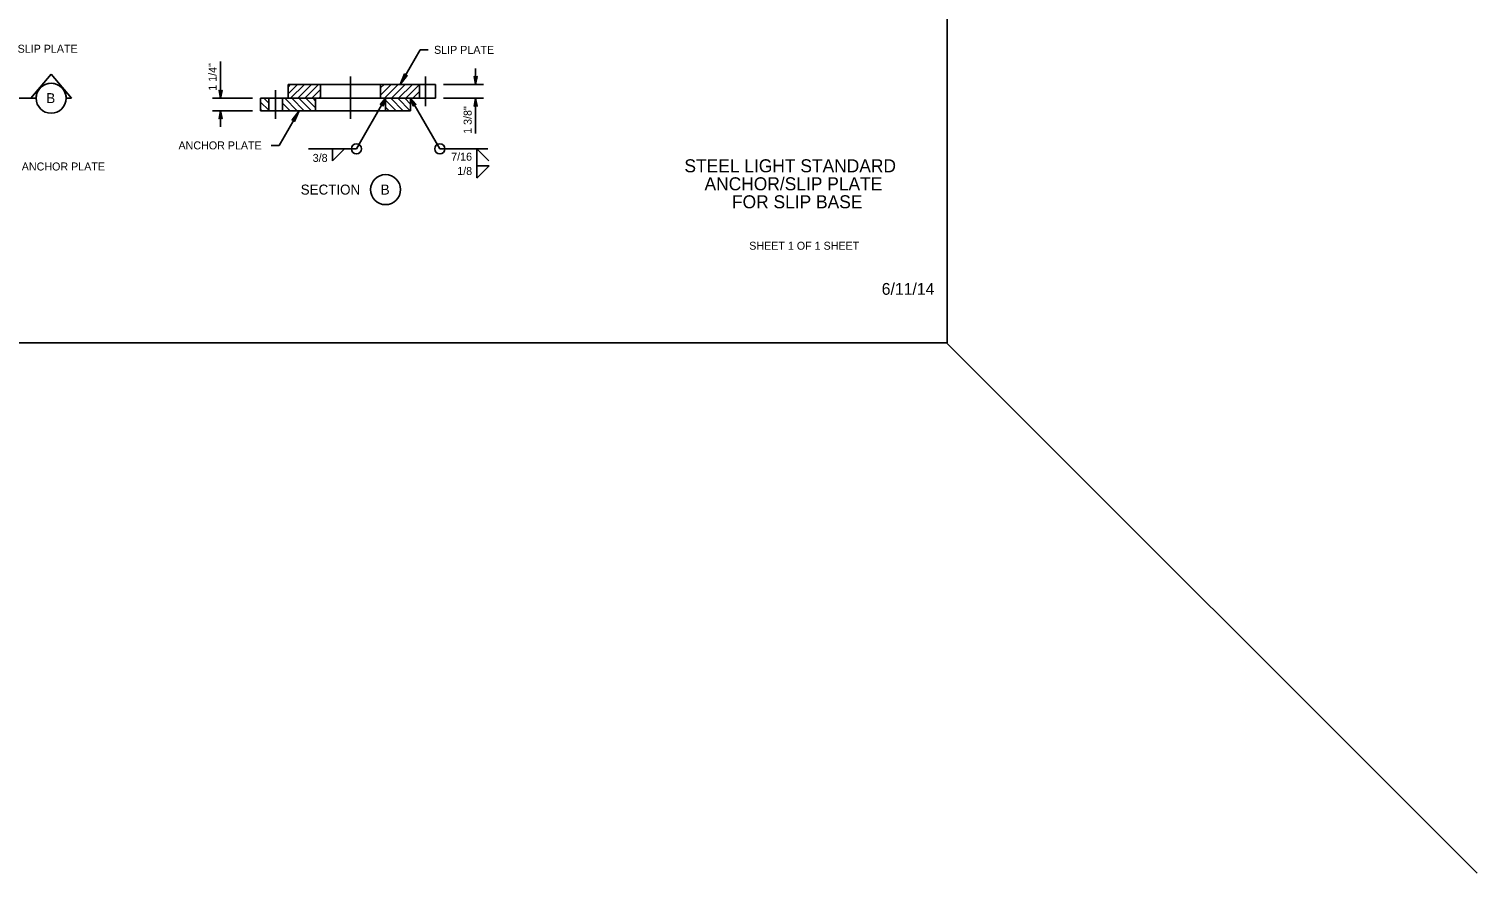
# Model space of a CAD drawing. Extents: x 99862 to 104211, y 98939 to 102076.
# Drawn here: x 101315 to 104211, y 98939 to 100627 of the extents above; entities that cross this region are included whole.
import ezdxf

# ---------------------------------------------------------------- set-up
doc = ezdxf.new("R2010")
doc.units = 0
for name, color, linetype in [('Level 1', 7, 'Continuous'), ('Level 10', 7, 'Continuous'), ('Level 15', 7, 'Continuous'), ('Level 20', 7, 'Continuous'), ('Level 3', 7, 'Continuous'), ('Level 4', 7, 'Continuous'), ('Level 62', 7, 'Continuous'), ('Level 63', 7, 'Continuous'), ('Level 9', 7, 'Continuous')]:
    doc.layers.add(name, color=color, linetype=linetype)

msp = doc.modelspace()

# ---------------------------------------------------------------- linework, layer by layer
at = {"layer": 'Level 1'}
msp.add_line((103150, 100000), (104210.7, 98939.3), dxfattribs=at)
msp.add_lwpolyline([(99862, 99999.5), (103151, 99999.5), (103151, 102075.5), (99862, 102075.5)], close=True, dxfattribs=at)
at = {"layer": 'Level 10'}
for p, q in [((102028.4, 100488.9), (101970, 100387.7)), ((102078.4, 100488.9), (102136.8, 100387.7)), ((101970, 100387.7), (101874, 100387.7)), ((101922, 100387.7), (101922, 100363.7)), ((101946.2, 100387.7), (101922, 100363.5)), ((102136.8, 100387.7), (102232.8, 100387.7)), ((102211, 100353.5), (102211, 100387.7)), ((102235, 100363.5), (102211, 100387.5)), ((102211, 100353.5), (102211, 100329.5)), ((102235.2, 100353.5), (102211, 100329.3)), ((102211, 100353.5), (102235.2, 100353.5))]:
    msp.add_line(p, q, dxfattribs=at)
for points in [[(102028.4, 100488.9), (102017.9, 100476.8), (102020.9, 100475.9), (102023.2, 100473.7)], [(102078.4, 100488.9), (102088.9, 100476.8), (102085.9, 100475.9), (102083.6, 100473.7)]]:
    msp.add_lwpolyline(points, close=True, dxfattribs=at)
for centre in [(101970, 100387.7), (102136.8, 100387.7)]:
    msp.add_circle(centre, 10, dxfattribs=at)
at = {"layer": 'Level 15'}
for p, q in [((101698.4, 100562.7), (101698.4, 100488.9)), ((102057.2, 100516.4), (102097.2, 100585.7)), ((102097.2, 100585.7), (102113.2, 100585.7)), ((101958.4, 100447.9), (101958.4, 100532.4)), ((102108.4, 100472.9), (102108.4, 100532.4)), ((102208.4, 100516.4), (102208.4, 100548.4)), ((101808.4, 100447.9), (101808.4, 100504.9)), ((102144.4, 100516.4), (102224.4, 100516.4)), ((101682.4, 100488.9), (101762.4, 100488.9)), ((102144.4, 100488.9), (102224.4, 100488.9)), ((102208.4, 100418.4), (102208.4, 100488.9)), ((101682.4, 100463.9), (101762.4, 100463.9)), ((101698.4, 100463.9), (101698.4, 100431.9)), ((101855.3, 100463.9), (101815.3, 100394.6)), ((101815.3, 100394.6), (101799.3, 100394.6))]:
    msp.add_line(p, q, dxfattribs=at)
for points in [[(102057.2, 100516.4), (102066, 100537.6), (102068, 100535.2), (102071.2, 100534.7)], [(102208.4, 100516.4), (102205.3, 100532.1), (102208.4, 100531.4), (102211.5, 100532.1)], [(101698.4, 100488.9), (101695.3, 100504.6), (101698.4, 100503.9), (101701.5, 100504.6)], [(102208.4, 100488.9), (102205.3, 100473.1), (102208.4, 100473.9), (102211.5, 100473.1)], [(101698.4, 100463.9), (101695.3, 100448.1), (101698.4, 100448.9), (101701.5, 100448.1)], [(101855.3, 100463.9), (101846.5, 100442.6), (101844.4, 100445), (101841.3, 100445.6)]]:
    msp.add_lwpolyline(points, close=True, dxfattribs=at)
at = {"layer": 'Level 3'}
for p, q in [((101778.4, 100481.1), (101794.7, 100464.9)), ((101784.8, 100488.9), (101794.7, 100479)), ((101794.7, 100488.9), (101822.2, 100488.9)), ((101822.2, 100479.2), (101837.5, 100463.9)), ((101826.6, 100488.9), (101851.6, 100463.9)), ((101840.8, 100488.9), (101865.8, 100463.9)), ((101854.9, 100488.9), (101879.9, 100463.9)), ((101869, 100488.9), (101888.4, 100469.5)), ((101883.2, 100488.9), (101888.4, 100483.6)), ((102028.4, 100488.9), (102028.4, 100488.9)), ((102028.4, 100484.9), (102049.5, 100463.9)), ((102038.6, 100488.9), (102063.6, 100463.9)), ((102052.7, 100488.9), (102077.7, 100463.9)), ((102066.9, 100488.9), (102078.4, 100477.3)), ((101778.4, 100467), (101781.5, 100463.9)), ((101794.7, 100463.9), (101822.2, 100463.9)), ((101822.2, 100465), (101823.3, 100463.9)), ((101888.4, 100463.9), (102028.4, 100463.9)), ((102028.4, 100470.8), (102035.3, 100463.9))]:
    msp.add_line(p, q, dxfattribs=at)
at = {"layer": 'Level 4'}
for p, q in [((101898.4, 100516.4), (101833.4, 100516.4)), ((101833.4, 100488.9), (101833.4, 100516.4)), ((101833.4, 100512), (101837.7, 100516.4)), ((101833.4, 100497.9), (101851.9, 100516.4)), ((101838.5, 100488.9), (101866, 100516.4)), ((101852.7, 100488.9), (101880.2, 100516.4)), ((101866.8, 100488.9), (101894.3, 100516.4)), ((101880.9, 100488.9), (101898.4, 100506.3)), ((101898.4, 100516.4), (102018.4, 100516.4)), ((101898.4, 100516.4), (101898.4, 100488.9)), ((102018.4, 100516.4), (102018.4, 100488.9)), ((102095.9, 100516.4), (102018.4, 100516.4)), ((102018.4, 100509.5), (102025.3, 100516.4)), ((102018.4, 100495.3), (102039.4, 100516.4)), ((102026.1, 100488.9), (102053.6, 100516.4)), ((102040.2, 100488.9), (102067.7, 100516.4)), ((102054.4, 100488.9), (102081.9, 100516.4)), ((102068.5, 100488.9), (102095.9, 100516.3)), ((102082.7, 100488.9), (102095.9, 100502.1)), ((102128.4, 100516.4), (102095.9, 100516.4)), ((102095.9, 100488.9), (102095.9, 100516.4)), ((102128.4, 100488.9), (102128.4, 100516.4)), ((101794.7, 100488.9), (101778.4, 100488.9)), ((101778.4, 100488.9), (101778.4, 100463.9)), ((101794.7, 100488.9), (101794.7, 100463.9)), ((101822.2, 100488.9), (101822.2, 100463.9)), ((101888.4, 100488.9), (101822.2, 100488.9)), ((101898.4, 100488.9), (101888.4, 100488.9)), ((101888.4, 100463.9), (101888.4, 100488.9)), ((101895.1, 100488.9), (101898.4, 100492.2)), ((101898.4, 100488.9), (102018.4, 100488.9)), ((102028.4, 100488.9), (102018.4, 100488.9)), ((102078.4, 100488.9), (102028.4, 100488.9)), ((102028.4, 100463.9), (102028.4, 100488.9)), ((102078.4, 100488.9), (102078.4, 100463.9)), ((102095.9, 100488.9), (102078.4, 100488.9)), ((102128.4, 100488.9), (102095.9, 100488.9)), ((101794.7, 100463.9), (101778.4, 100463.9)), ((101888.4, 100463.9), (101822.2, 100463.9)), ((102078.4, 100463.9), (102028.4, 100463.9))]:
    msp.add_line(p, q, dxfattribs=at)
at = {"layer": 'Level 9'}
for p, q in [((101359.6, 100537.3), (101319, 100488.9)), ((101400.2, 100488.9), (101359.6, 100537.3)), ((100848, 100488.9), (101329.6, 100488.9)), ((101319, 100488.9), (101329.6, 100488.9)), ((101389.6, 100488.9), (101400.2, 100488.9))]:
    msp.add_line(p, q, dxfattribs=at)
for centre in [(101359.6, 100488.9), (102028.2, 100306.1)]:
    msp.add_circle(centre, 30, dxfattribs=at)
msp.add_arc((101359.6, 100488.9), 30, 359.9978, 180.0022, dxfattribs=at)

# ---------------------------------------------------------------- texts
at = {"layer": 'Level 1'}
msp.add_text('6/11/14', height=23.62, dxfattribs=at).set_placement((103020.3, 100095.8))
at = {"layer": 'Level 10'}
for s, p in [('3/8', (101882.6, 100361.6)), ('7/16', (102159.5, 100364)), ('1/8', (102171.6, 100335.4))]:
    msp.add_text(s, height=16, rotation=360, dxfattribs=at).set_placement(p)
at = {"layer": 'Level 20'}
for s, height, p in [('SLIP PLATE', 16, (101292.5, 100579.9)), ('SLIP PLATE', 16, (102125.2, 100577.7)), ('B', 20, (101349.9, 100479.1)), ('SECTION', 20, (101858.6, 100296.2)), ('B', 20, (102018.6, 100296.2))]:
    msp.add_text(s, height=height, dxfattribs=at).set_placement(p)
for s, rotation, p in [('1 1/4"', 90, (101690.4, 100503.9)), ('1 3/8"', 90, (102200.4, 100417.7)), ('ANCHOR PLATE', 360, (101614.2, 100386.6)), ('ANCHOR PLATE', 360, (101300.8, 100344.4))]:
    msp.add_text(s, height=16, rotation=rotation, dxfattribs=at).set_placement(p)
at = {"layer": 'Level 62'}
msp.add_text('SHEET 1 OF 1 SHEET', height=16, dxfattribs=at).set_placement((102755.4, 100185.9))
at = {"layer": 'Level 63'}
for s, p in [('STEEL LIGHT STANDARD', (102625.8, 100340.8)), ('ANCHOR/SLIP PLATE', (102666, 100304.8)), ('FOR SLIP BASE', (102720.9, 100268.8))]:
    msp.add_text(s, height=26, dxfattribs=at).set_placement(p)

doc.saveas('drawing.dxf')
